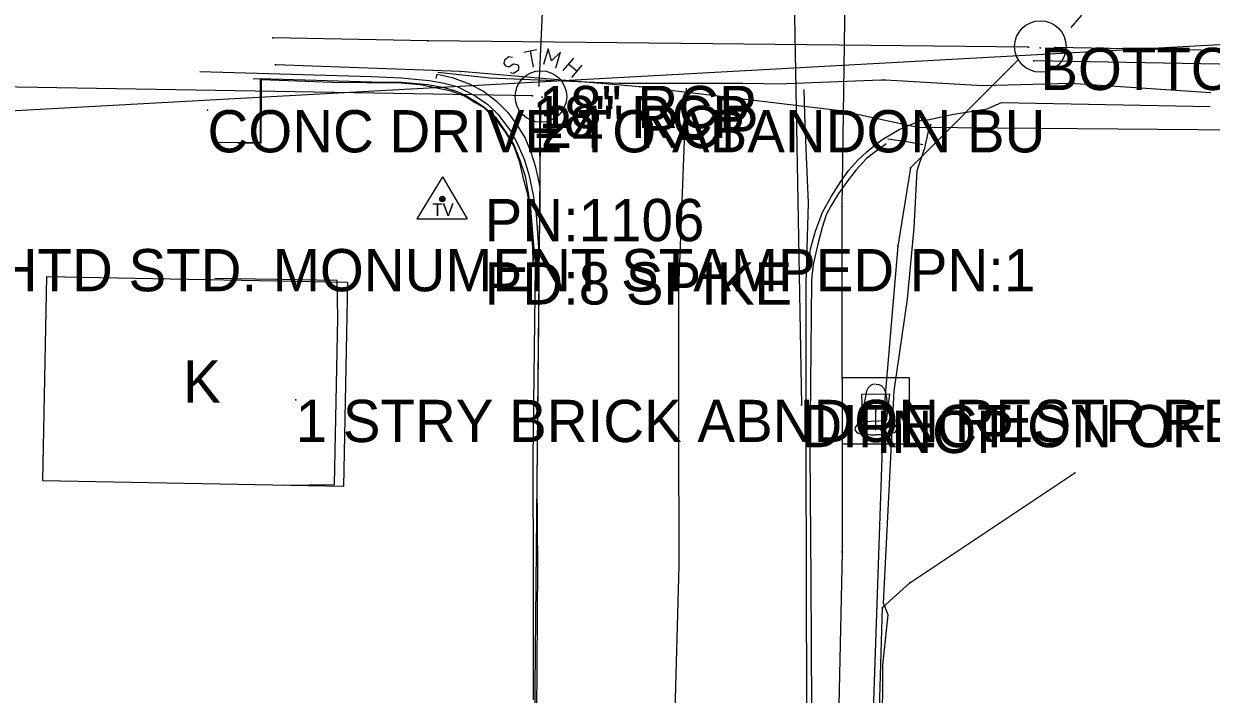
# Model space of a CAD drawing. Extents: x 1304270 to 1306561, y 1876019 to 1876752.
# Drawn here: x 1304900.2 to 1305040.8, y 1876324.4 to 1876403.7 of the extents above; entities that cross this region are included whole.
import ezdxf

# ---------------------------------------------------------------- set-up
doc = ezdxf.new("R2010")
doc.units = 0
for name, color, linetype in [('Default', 7, 'Continuous'), ('S_BUILDING', 7, 'Continuous'), ('S_BUILDING_ANNOT', 7, 'Continuous'), ('S_CURB', 7, 'Continuous'), ('S_EDGE_CONCRETE', 7, 'Continuous'), ('S_EDGE_PAVEMENT', 7, 'Continuous'), ('S_FIBER_OPTIC_CABLE', 7, 'Continuous'), ('S_GAS_UTILITIES', 7, 'Continuous'), ('S_MANHOLE_ANNOT', 7, 'Continuous'), ('S_MSC_PT_SYM', 7, 'Continuous'), ('S_PARKING', 7, 'Continuous'), ('S_PAVEMENT_CROWN', 7, 'Continuous'), ('S_PRIMARY_CTL_ANNOT', 7, 'Continuous'), ('S_SECONDARY_CTL', 7, 'Continuous'), ('S_SECONDARY_CTL_ANNOT', 7, 'Continuous'), ('S_STORM_SEWER', 7, 'Continuous'), ('S_STORM_SEWER_ANNOT', 7, 'Continuous'), ('S_STR_PT_SYM', 7, 'Continuous'), ('S_SURVEY_TEXT_ANNOT', 7, 'Continuous'), ('S_TELEPHONE_UTILITIES', 7, 'Continuous'), ('S_TELEPHONE_UTILITIES_ANNOT', 7, 'Continuous'), ('S_UTL_PT_SYM', 7, 'Continuous'), ('S_WATER_UTILITIES', 7, 'Continuous'), ('S_WATER_UTILITIES_ANNOT', 7, 'Continuous')]:
    doc.layers.add(name, color=color, linetype=linetype)

msp = doc.modelspace()

# ---------------------------------------------------------------- linework, layer by layer
at = {"layer": 'Default'}
msp.add_line((1304873.94, 1876392.06), (1305473.53, 1876424.94), dxfattribs=at)
at = {"layer": 'S_BUILDING'}
msp.add_lwpolyline([(1304938.09, 1876348.94), (1304902.49, 1876349.63), (1304902.96, 1876373.81), (1304938.56, 1876373.12)], close=True, dxfattribs=at)
at = {"layer": 'S_CURB'}
for points in [[(1304927.39, 1876397.21), (1304928.23, 1876397.26), (1304941.45, 1876396.87), (1304945.01, 1876396.81), (1304948.12, 1876396.53), (1304949.99, 1876396.19), (1304951.23, 1876395.82), (1304952.47, 1876395.32), (1304953.34, 1876394.76), (1304953.65, 1876394.6), (1304954.77, 1876393.85), (1304956.08, 1876392.65), (1304957.25, 1876391.01), (1304958.26, 1876389.41), (1304958.97, 1876387.57), (1304959.61, 1876385.67), (1304960.01, 1876383.48), (1304960.31, 1876380.87), (1304960.59, 1876377.48), (1304960.64, 1876377.09), (1304960.63, 1876376.2), (1304960.61, 1876375.73)], [(1305002.33, 1876389.51), (1305000.99, 1876388.54), (1305000.03, 1876387.77), (1304998.78, 1876386.42), (1304997.67, 1876385.02), (1304996.71, 1876383.64), (1304995.81, 1876382.15), (1304995.25, 1876381.09), (1304994.76, 1876379.59), (1304994.22, 1876377.46), (1304993.74, 1876375.44), (1304993.56, 1876373.88), (1304993.51, 1876373.22), (1304993.31, 1876353.04), (1304993.41, 1876337.87), (1304993.52, 1876322.71), (1304993.56, 1876303.33), (1304993.6, 1876283.94), (1304993.53, 1876272.49)]]:
    msp.add_lwpolyline(points, dxfattribs=at)
at = {"layer": 'S_EDGE_CONCRETE'}
msp.add_lwpolyline([(1304949.08, 1876397.24), (1304949.2, 1876397.76), (1304950.95, 1876397.38), (1304952.99, 1876396.62), (1304954.66, 1876395.76), (1304956.2, 1876394.55), (1304957.56, 1876393.23), (1304958.7, 1876391.63), (1304959.59, 1876390.17), (1304960.28, 1876388.51), (1304960.8, 1876386.89), (1304961.15, 1876385.33), (1304961.35, 1876384.35)], dxfattribs=at)
msp.add_lwpolyline([(1305002.33, 1876356.71), (1304999.58, 1876356.62), (1304999.47, 1876359.89), (1305002.74, 1876359.91)], close=True, dxfattribs=at)
at = {"layer": 'S_EDGE_PAVEMENT'}
for points in [[(1304921.08, 1876398.08), (1304941.42, 1876397.48), (1304944.92, 1876397.33), (1304948.22, 1876397.01), (1304950.03, 1876396.7), (1304951.56, 1876396.28), (1304952.69, 1876395.71), (1304953.79, 1876395.11), (1304955.18, 1876394.18), (1304956.38, 1876393.01), (1304957.85, 1876391.07), (1304958.58, 1876389.76), (1304959.47, 1876387.71), (1304960.03, 1876385.9), (1304960.55, 1876383.45), (1304960.9, 1876381.11), (1304961.18, 1876377.28), (1304961.18, 1876375.89), (1304960.92, 1876374.59)], [(1304949.28, 1876398), (1304955.42, 1876397.32), (1304970.7, 1876396.69), (1304985.37, 1876396.68), (1304990.28, 1876396.62), (1304990.56, 1876396.67), (1305001.76, 1876397.1), (1305002.26, 1876397.1), (1305013.78, 1876396.43), (1305024.16, 1876396.69), (1305040.77, 1876395.58)], [(1304928.23, 1876397.11), (1304928.22, 1876389.68)], [(1304992.58, 1876395.95), (1304992.67, 1876392.97), (1304992.89, 1876387.96), (1304993.12, 1876382.52), (1304992.95, 1876377.14), (1304992.83, 1876373.03), (1304992.83, 1876353.07), (1304992.88, 1876337.99), (1304992.93, 1876322.91), (1304993, 1876303.41), (1304993.07, 1876283.92), (1304993.07, 1876272.99), (1304992.49, 1876271.71), (1304992.46, 1876268.84), (1304992.98, 1876268.15), (1304993.15, 1876253.51), (1304993.2, 1876248.53), (1304993.13, 1876247.77), (1304993.23, 1876236.09), (1304993.14, 1876235.17), (1304993.16, 1876210.69)], [(1304961.3, 1876394.03), (1304961.33, 1876382.17), (1304961.23, 1876375.71), (1304961.22, 1876372.29), (1304960.99, 1876349.53), (1304961.06, 1876339.46), (1304960.95, 1876322), (1304961.28, 1876298.1), (1304961.25, 1876276.13), (1304961.53, 1876271.86), (1304961.62, 1876270.95), (1304961.87, 1876268.65), (1304961.43, 1876268.03), (1304961.3, 1876262.61), (1304961.21, 1876261.58), (1304961.4, 1876239.81), (1304961.49, 1876224.87), (1304961.47, 1876212.95)], [(1304993.19, 1876375.29), (1304993.37, 1876377.09), (1304993.99, 1876379.17), (1304994.81, 1876381.41), (1304995.86, 1876383.3), (1304996.97, 1876385.06), (1304997.93, 1876386.41), (1304998.99, 1876387.59), (1305000.06, 1876388.55), (1305001.22, 1876389.57), (1305001.95, 1876390.08), (1305003.88, 1876391.19), (1305006.54, 1876392.3), (1305007.47, 1876392.39), (1305010.11, 1876393), (1305014.3, 1876393.66), (1305015.98, 1876394.42), (1305040.71, 1876393.94)], [(1305001.91, 1876319.75), (1305001.96, 1876327.81), (1305002.59, 1876333.77), (1305002.01, 1876335.14), (1305002.65, 1876347.7), (1305003.29, 1876360.27), (1305004.88, 1876371.11), (1305005.64, 1876379.58), (1305006, 1876386.36), (1305006.93, 1876389.03), (1305007.34, 1876390.96), (1305007.66, 1876391.86)], [(1304922.9, 1876389.71), (1304928.22, 1876389.68)], [(1305006.67, 1876389.4), (1305004.78, 1876389.75), (1305002.55, 1876390.06)], [(1304931.08, 1876349.11), (1304937.05, 1876349.17), (1304937.41, 1876368.86), (1304937.34, 1876373.33), (1304922.87, 1876373.56)]]:
    msp.add_lwpolyline(points, dxfattribs=at)
at = {"layer": 'S_FIBER_OPTIC_CABLE'}
for p, q in [((1304997.81, 1876430.58), (1304997.1, 1876382.1)), ((1304948.07, 1876401.72), (1304929.73, 1876402.04)), ((1305019.2, 1876400.94), (1304948.07, 1876401.72)), ((1305060.48, 1876400.23), (1305022.32, 1876400.93)), ((1305017.97, 1876399.46), (1305005.21, 1876386.67)), ((1305352.56, 1876393.61), (1305019.82, 1876399.32)), ((1305005.21, 1876386.67), (1305003.72, 1876377.41)), ((1304997.1, 1876382.1), (1304997.12, 1876341.23)), ((1305003.72, 1876377.41), (1305001.98, 1876356.98)), ((1305001.98, 1876356.98), (1304999.02, 1876271.02)), ((1304997.12, 1876341.23), (1304995.58, 1876266.56))]:
    msp.add_line(p, q, dxfattribs=at)
at = {"layer": 'S_GAS_UTILITIES'}
for p, q in [((1304951.95, 1876398.08), (1304930.05, 1876398.88)), ((1304973.18, 1876396.27), (1304951.95, 1876398.08)), ((1304996.9, 1876393.42), (1304973.18, 1876396.27)), ((1305006.09, 1876391.43), (1304996.9, 1876393.42)), ((1305058.95, 1876391.01), (1305006.09, 1876391.43)), ((1305005.14, 1876337.56), (1305024.68, 1876350.56)), ((1305001.91, 1876334.61), (1305005.14, 1876337.56)), ((1305000.96, 1876303.41), (1305001.91, 1876334.61))]:
    msp.add_line(p, q, dxfattribs=at)
at = {"layer": 'S_MSC_PT_SYM'}
msp.add_lwpolyline([(1304922, 1876393.5), (1304922, 1876393.55), (1304922, 1876393.5), (1304921.95, 1876393.5), (1304922, 1876393.5), (1304922, 1876393.45), (1304922, 1876393.5), (1304922.05, 1876393.5)], dxfattribs=at)
at = {"layer": 'S_PARKING'}
msp.add_lwpolyline([(1304925.57, 1876389.63), (1304928.34, 1876389.64), (1304928.37, 1876395.47), (1304928.37, 1876397.13), (1304936.79, 1876396.83), (1304944.91, 1876396.75), (1304947.18, 1876396.52), (1304948.94, 1876396.17), (1304950.79, 1876395.8), (1304952.51, 1876395.14), (1304953.68, 1876394.41), (1304954.71, 1876393.81), (1304956, 1876392.53), (1304957.2, 1876390.97), (1304958.26, 1876389.23), (1304958.91, 1876387.46), (1304959.34, 1876385.57), (1304959.9, 1876383.56), (1304960.23, 1876380.67), (1304960.47, 1876377.2), (1304960.53, 1876375.52), (1304960.79, 1876375.36), (1304960.77, 1876374.92), (1304960.52, 1876352.35), (1304960.55, 1876338.03), (1304960.57, 1876323.7)], dxfattribs=at)
at = {"layer": 'S_PAVEMENT_CROWN'}
msp.add_lwpolyline([(1304978.68, 1876396.09), (1304977.75, 1876372.31), (1304977.76, 1876355.96), (1304977.78, 1876339.61), (1304977.29, 1876320.92), (1304976.79, 1876302.23), (1304977.44, 1876281.07), (1304978.08, 1876259.92), (1304978.16, 1876244.79), (1304978.24, 1876229.66), (1304977.14, 1876211.47)], dxfattribs=at)
at = {"layer": 'S_SECONDARY_CTL'}
for p, q in [((1304949.8, 1876385.6), (1304946.79, 1876380.65)), ((1304949.8, 1876385.6), (1304952.75, 1876380.65)), ((1304946.79, 1876380.65), (1304952.75, 1876380.65))]:
    msp.add_line(p, q, dxfattribs=at)
for radius in [0.311, 0.183, 0.103]:
    msp.add_circle((1304949.8, 1876382.99), radius, dxfattribs=at)
at = {"layer": 'S_STORM_SEWER'}
for p, q in [((1304962.76, 1876429.27), (1304961.22, 1876396.37)), ((1304957.14, 1876399.42), (1304957.06, 1876399.03)), ((1304957.68, 1876399.8), (1304957.14, 1876399.42)), ((1304958.11, 1876399.73), (1304957.68, 1876399.8)), ((1304959.43, 1876400.38), (1304960.94, 1876400.66)), ((1304960.2, 1876400.54), (1304960.55, 1876398.6)), ((1304964.12, 1876398.18), (1304965.36, 1876399.65)), ((1304960.46, 1876395.19), (1304801.23, 1876397.91)), ((1304957.06, 1876399.03), (1304957.26, 1876398.76)), ((1304957.26, 1876398.76), (1304957.68, 1876398.64)), ((1304957.68, 1876398.64), (1304958.23, 1876398.99)), ((1304958.23, 1876397.83), (1304957.84, 1876397.9)), ((1304958.23, 1876398.99), (1304958.69, 1876398.91)), ((1304958.77, 1876398.21), (1304958.23, 1876397.83)), ((1304958.69, 1876398.91), (1304958.85, 1876398.64)), ((1304958.85, 1876398.64), (1304958.77, 1876398.21)), ((1304964.78, 1876398.95), (1304965.74, 1876398.14)), ((1304966.33, 1876398.83), (1304965.09, 1876397.36)), ((1304960.28, 1876270.66), (1304961.45, 1876394.01))]:
    msp.add_line(p, q, dxfattribs=at)
msp.add_lwpolyline([(1304963.23, 1876398.49), (1304963.77, 1876400.35), (1304962.72, 1876399.34), (1304962.33, 1876400.77), (1304961.79, 1876398.91)], dxfattribs=at)
msp.add_circle((1304961.47, 1876395.11), 3.05, dxfattribs=at)
at = {"layer": 'S_STR_PT_SYM'}
msp.add_lwpolyline([(1304932.44, 1876359.21), (1304932.44, 1876359.26), (1304932.44, 1876359.21), (1304932.39, 1876359.21), (1304932.44, 1876359.21), (1304932.44, 1876359.16), (1304932.44, 1876359.21), (1304932.49, 1876359.21)], dxfattribs=at)
at = {"layer": 'S_TELEPHONE_UTILITIES'}
for p, q in [((1304997.18, 1876361.84), (1305005.05, 1876361.84)), ((1304997.18, 1876353.97), (1304997.18, 1876361.84)), ((1305005.05, 1876361.84), (1305005.05, 1876353.97)), ((1305001.08, 1876358.34), (1305000.03, 1876358.34)), ((1305002.14, 1876358.34), (1305001.08, 1876358.34)), ((1305001.08, 1876358.34), (1305001.08, 1876355.61)), ((1305005.05, 1876353.97), (1304997.18, 1876353.97))]:
    msp.add_line(p, q, dxfattribs=at)
for points in [[(1305001.08, 1876361.07), (1305000.74, 1876361.04), (1305000.5, 1876360.91), (1305000.22, 1876360.63), (1305000, 1876360.23), (1304999.84, 1876359.39), (1304999.75, 1876358.8), (1304999.6, 1876357.97), (1304999.47, 1876357.44), (1304999.38, 1876357.01), (1304999.29, 1876356.7), (1304999.19, 1876356.51), (1304998.91, 1876356.26), (1304998.7, 1876356.01), (1304998.64, 1876355.77), (1304998.73, 1876355.52), (1304998.91, 1876355.3), (1304999.29, 1876355.21), (1304999.88, 1876355.18), (1305000.53, 1876355.08), (1305001.12, 1876355.05)], [(1305001.15, 1876361.07), (1305001.49, 1876361.04), (1305001.74, 1876360.91), (1305002.01, 1876360.63), (1305002.23, 1876360.23), (1305002.39, 1876359.39), (1305002.48, 1876358.8), (1305002.63, 1876357.97), (1305002.76, 1876357.44), (1305002.85, 1876357.01), (1305002.94, 1876356.7), (1305003.04, 1876356.51), (1305003.32, 1876356.26), (1305003.53, 1876356.01), (1305003.6, 1876355.77), (1305003.5, 1876355.52), (1305003.32, 1876355.3), (1305002.94, 1876355.21), (1305002.36, 1876355.18), (1305001.7, 1876355.08), (1305001.12, 1876355.05)], [(1305001.12, 1876357.91), (1305001.12, 1876357.96), (1305001.12, 1876357.91), (1305001.07, 1876357.91), (1305001.12, 1876357.91), (1305001.12, 1876357.86), (1305001.12, 1876357.91), (1305001.17, 1876357.91)]]:
    msp.add_lwpolyline(points, dxfattribs=at)
at = {"layer": 'S_TELEPHONE_UTILITIES_ANNOT'}
msp.add_line((1305025.45, 1876404.75), (1305024.21, 1876403.28), dxfattribs=at)
msp.add_circle((1305020.6, 1876401.03), 3.05, dxfattribs=at)
at = {"layer": 'S_UTL_PT_SYM'}
for points in [[(1304929.73, 1876402.04), (1304929.73, 1876402.09), (1304929.73, 1876402.04), (1304929.68, 1876402.04), (1304929.73, 1876402.04), (1304929.73, 1876401.99), (1304929.73, 1876402.04), (1304929.78, 1876402.04)], [(1304948.07, 1876401.72), (1304948.07, 1876401.77), (1304948.07, 1876401.72), (1304948.02, 1876401.72), (1304948.07, 1876401.72), (1304948.07, 1876401.67), (1304948.07, 1876401.72), (1304948.12, 1876401.72)], [(1305019.2, 1876400.94), (1305019.2, 1876400.99), (1305019.2, 1876400.94), (1305019.15, 1876400.94), (1305019.2, 1876400.94), (1305019.2, 1876400.89), (1305019.2, 1876400.94), (1305019.25, 1876400.94)], [(1305020.59, 1876400.88), (1305020.59, 1876400.93), (1305020.59, 1876400.88), (1305020.54, 1876400.88), (1305020.59, 1876400.88), (1305020.59, 1876400.83), (1305020.59, 1876400.88), (1305020.64, 1876400.88)], [(1305022.32, 1876400.93), (1305022.32, 1876400.98), (1305022.32, 1876400.93), (1305022.27, 1876400.93), (1305022.32, 1876400.93), (1305022.32, 1876400.88), (1305022.32, 1876400.93), (1305022.37, 1876400.93)], [(1305017.97, 1876399.46), (1305017.97, 1876399.51), (1305017.97, 1876399.46), (1305017.92, 1876399.46), (1305017.97, 1876399.46), (1305017.97, 1876399.41), (1305017.97, 1876399.46), (1305018.02, 1876399.46)], [(1305019.82, 1876399.32), (1305019.82, 1876399.37), (1305019.82, 1876399.32), (1305019.77, 1876399.32), (1305019.82, 1876399.32), (1305019.82, 1876399.27), (1305019.82, 1876399.32), (1305019.87, 1876399.32)], [(1304930.05, 1876398.88), (1304930.05, 1876398.93), (1304930.05, 1876398.88), (1304930, 1876398.88), (1304930.05, 1876398.88), (1304930.05, 1876398.83), (1304930.05, 1876398.88), (1304930.1, 1876398.88)], [(1304951.95, 1876398.08), (1304951.95, 1876398.13), (1304951.95, 1876398.08), (1304951.9, 1876398.08), (1304951.95, 1876398.08), (1304951.95, 1876398.03), (1304951.95, 1876398.08), (1304952, 1876398.08)], [(1304960.46, 1876395.19), (1304960.46, 1876395.24), (1304960.46, 1876395.19), (1304960.41, 1876395.19), (1304960.46, 1876395.19), (1304960.46, 1876395.14), (1304960.46, 1876395.19), (1304960.51, 1876395.19)], [(1304961.22, 1876396.37), (1304961.22, 1876396.42), (1304961.22, 1876396.37), (1304961.17, 1876396.37), (1304961.22, 1876396.37), (1304961.22, 1876396.32), (1304961.22, 1876396.37), (1304961.27, 1876396.37)], [(1304961.6, 1876395.05), (1304961.6, 1876395.1), (1304961.6, 1876395.05), (1304961.55, 1876395.05), (1304961.6, 1876395.05), (1304961.6, 1876395), (1304961.6, 1876395.05), (1304961.65, 1876395.05)], [(1304973.18, 1876396.27), (1304973.18, 1876396.32), (1304973.18, 1876396.27), (1304973.13, 1876396.27), (1304973.18, 1876396.27), (1304973.18, 1876396.22), (1304973.18, 1876396.27), (1304973.23, 1876396.27)], [(1304961.45, 1876394.01), (1304961.45, 1876394.06), (1304961.45, 1876394.01), (1304961.4, 1876394.01), (1304961.45, 1876394.01), (1304961.45, 1876393.96), (1304961.45, 1876394.01), (1304961.5, 1876394.01)], [(1304996.9, 1876393.42), (1304996.9, 1876393.47), (1304996.9, 1876393.42), (1304996.85, 1876393.42), (1304996.9, 1876393.42), (1304996.9, 1876393.37), (1304996.9, 1876393.42), (1304996.95, 1876393.42)], [(1305006.09, 1876391.43), (1305006.09, 1876391.48), (1305006.09, 1876391.43), (1305006.04, 1876391.43), (1305006.09, 1876391.43), (1305006.09, 1876391.38), (1305006.09, 1876391.43), (1305006.14, 1876391.43)], [(1305005.21, 1876386.67), (1305005.21, 1876386.72), (1305005.21, 1876386.67), (1305005.16, 1876386.67), (1305005.21, 1876386.67), (1305005.21, 1876386.62), (1305005.21, 1876386.67), (1305005.26, 1876386.67)], [(1304997.1, 1876382.1), (1304997.1, 1876382.15), (1304997.1, 1876382.1), (1304997.05, 1876382.1), (1304997.1, 1876382.1), (1304997.1, 1876382.05), (1304997.1, 1876382.1), (1304997.15, 1876382.1)], [(1305003.72, 1876377.41), (1305003.72, 1876377.46), (1305003.72, 1876377.41), (1305003.67, 1876377.41), (1305003.72, 1876377.41), (1305003.72, 1876377.36), (1305003.72, 1876377.41), (1305003.77, 1876377.41)], [(1304992.31, 1876358.6), (1304992.31, 1876358.65), (1304992.31, 1876358.6), (1304992.26, 1876358.6), (1304992.31, 1876358.6), (1304992.31, 1876358.55), (1304992.31, 1876358.6), (1304992.36, 1876358.6)], [(1305001.98, 1876356.98), (1305001.98, 1876357.03), (1305001.98, 1876356.98), (1305001.93, 1876356.98), (1305001.98, 1876356.98), (1305001.98, 1876356.93), (1305001.98, 1876356.98), (1305002.03, 1876356.98)], [(1305024.68, 1876350.56), (1305024.68, 1876350.61), (1305024.68, 1876350.56), (1305024.63, 1876350.56), (1305024.68, 1876350.56), (1305024.68, 1876350.51), (1305024.68, 1876350.56), (1305024.73, 1876350.56)], [(1304997.12, 1876341.23), (1304997.12, 1876341.28), (1304997.12, 1876341.23), (1304997.07, 1876341.23), (1304997.12, 1876341.23), (1304997.12, 1876341.18), (1304997.12, 1876341.23), (1304997.17, 1876341.23)], [(1305005.14, 1876337.56), (1305005.14, 1876337.61), (1305005.14, 1876337.56), (1305005.09, 1876337.56), (1305005.14, 1876337.56), (1305005.14, 1876337.51), (1305005.14, 1876337.56), (1305005.19, 1876337.56)], [(1305001.91, 1876334.61), (1305001.91, 1876334.66), (1305001.91, 1876334.61), (1305001.86, 1876334.61), (1305001.91, 1876334.61), (1305001.91, 1876334.56), (1305001.91, 1876334.61), (1305001.96, 1876334.61)]]:
    msp.add_lwpolyline(points, dxfattribs=at)
at = {"layer": 'S_WATER_UTILITIES'}
msp.add_line((1304991.18, 1876422.78), (1304992.31, 1876358.6), dxfattribs=at)

# ---------------------------------------------------------------- texts
at = {"layer": 'S_BUILDING_ANNOT'}
for s, p in [('K', (1304919.11, 1876358.87)), ('1 STRY BRICK ABNDON RESTR RESTRUNT', (1304932.44, 1876354.21))]:
    msp.add_text(s, height=5, dxfattribs=at).set_placement(p)
at = {"layer": 'S_MANHOLE_ANNOT'}
msp.add_text('BOTTOM OF HT', height=5, dxfattribs=at).set_placement((1305020.59, 1876395.88))
at = {"layer": 'S_PRIMARY_CTL_ANNOT'}
msp.add_text('PD:AHTD STD. MONUMENT STAMPED PN:1', height=5, dxfattribs=at).set_placement((1304881.44, 1876372.06))
at = {"layer": 'S_SECONDARY_CTL'}
msp.add_text('TV', height=1.5, rotation=360, dxfattribs=at).set_placement((1304948.6, 1876380.98))
at = {"layer": 'S_SECONDARY_CTL_ANNOT'}
for s, p in [('PN:1106', (1304954.8, 1876377.99)), ('PD:8 SPIKE', (1304954.8, 1876370.49))]:
    msp.add_text(s, height=5, dxfattribs=at).set_placement(p)
at = {"layer": 'S_STORM_SEWER_ANNOT'}
for s, p in [('18" RCP', (1304960.46, 1876390.19)), ('18" RCP', (1304961.22, 1876391.37)), ('24" RCP', (1304961.45, 1876389.01))]:
    msp.add_text(s, height=5, dxfattribs=at).set_placement(p)
at = {"layer": 'S_SURVEY_TEXT_ANNOT'}
msp.add_text('CONC DRIVE TO ABANDON BU', height=5, dxfattribs=at).set_placement((1304922, 1876388.5))
at = {"layer": 'S_TELEPHONE_UTILITIES_ANNOT'}
msp.add_text('INOP', height=5, dxfattribs=at).set_placement((1305001.12, 1876352.91))
at = {"layer": 'S_WATER_UTILITIES_ANNOT'}
msp.add_text('DIRECTION OF INFO GIVEN BY IMPL', height=5, dxfattribs=at).set_placement((1304992.31, 1876353.6))

doc.saveas('drawing.dxf')
